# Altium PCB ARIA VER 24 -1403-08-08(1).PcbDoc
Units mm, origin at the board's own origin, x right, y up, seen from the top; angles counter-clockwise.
Board outline 174.25 x 98.25 mm, 2 copper layers (Top Layer, Bottom Layer), stack 2.06 mm thick; 9 components, 12 nets, 45 pads, 0 vias.
Unrouted connection lines stored in the file: 13.
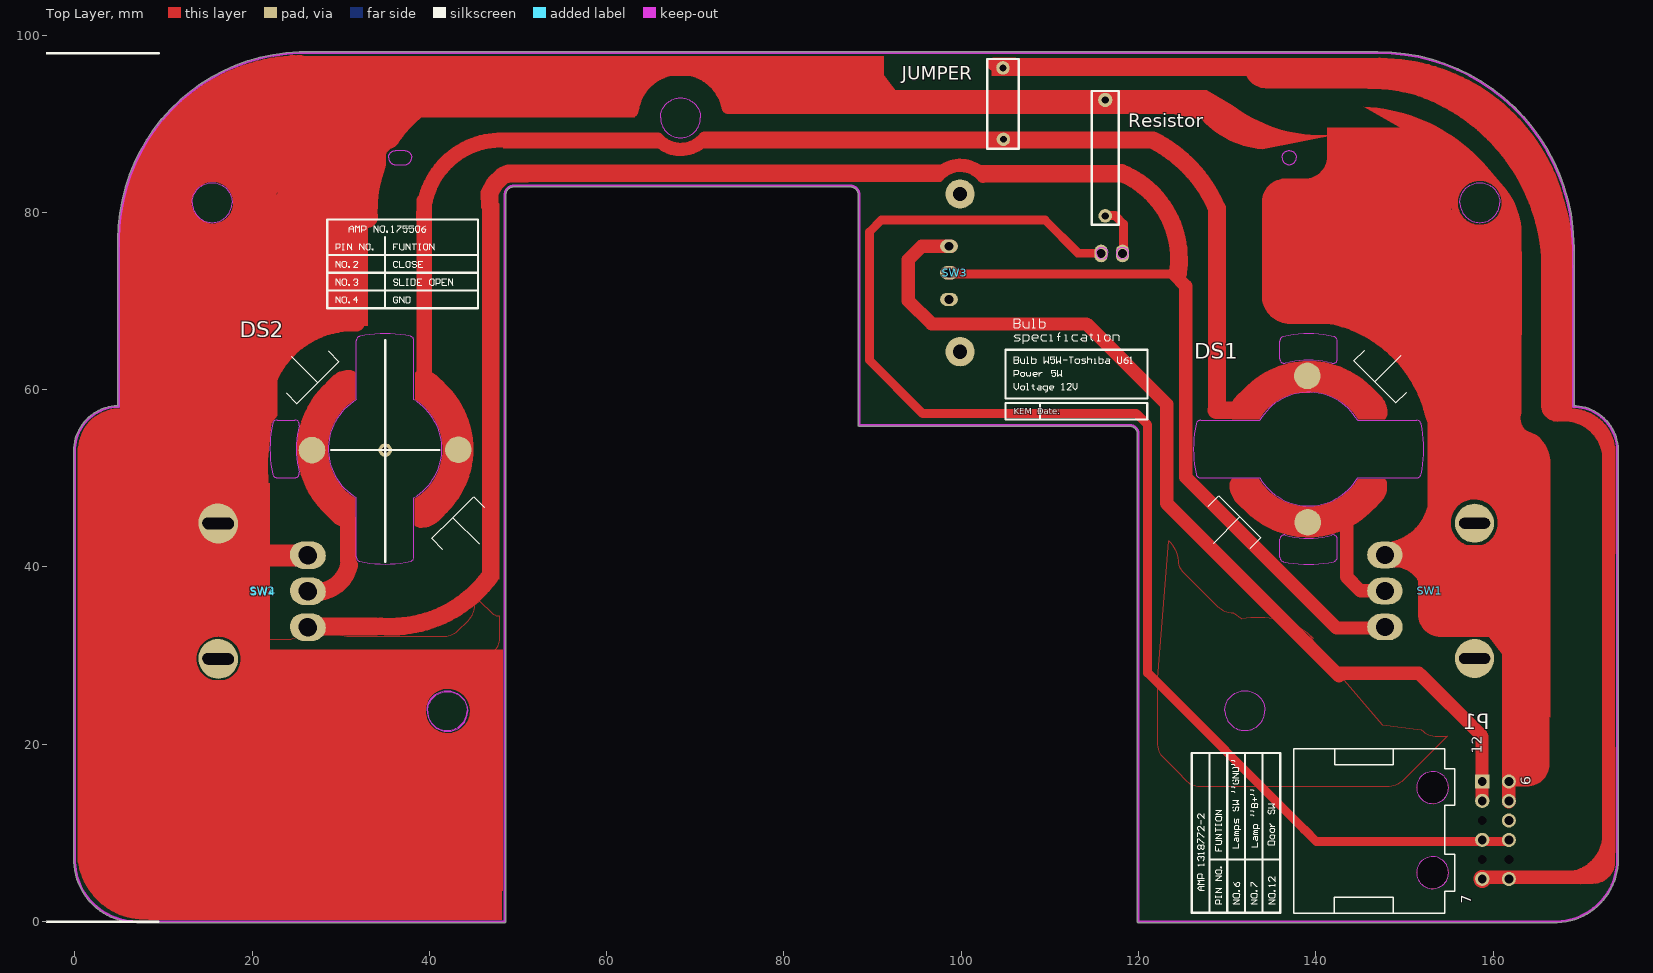
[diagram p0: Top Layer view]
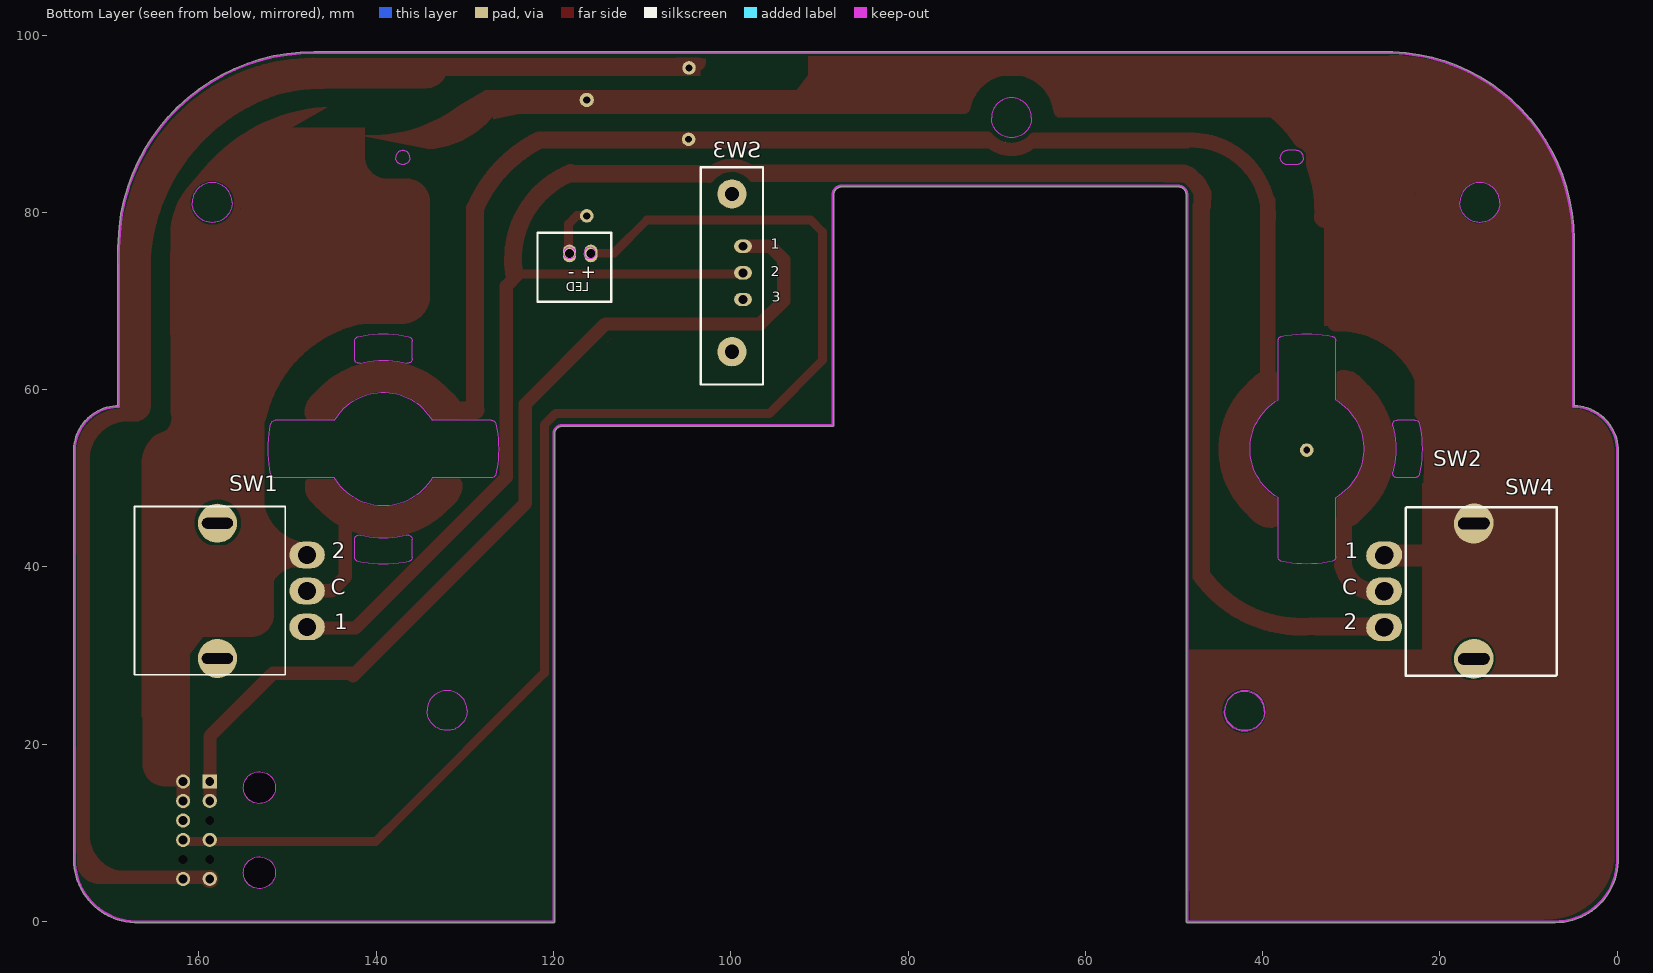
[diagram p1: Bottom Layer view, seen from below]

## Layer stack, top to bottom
Top Solder: solder mask 0.0102, Solder Resist, Dk 3.5
Top Layer: signal copper 0.16
Dielectric1: core 1.6, FR-4, Dk 4.8
Bottom Layer: signal copper 0.3
Bottom Solder: solder mask 0.0102, Solder Resist, Dk 3.5

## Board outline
655 vertices, not listed, extent -0.129,-0.129 174.126,98.126

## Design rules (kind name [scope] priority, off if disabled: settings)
AssemblyTestPointUsage [All] p1 off:
AssemblyTestpoint [All] p1 off: testpointundercomponent=TRUE minsize=1.016 maxsize=2.54 preferedsize=1.524 minholesize=0 maxholesize=1.016 preferedholesize=0.813 testpointgrid=0.025 usegrid=TRUE gridtolerance=0 allowsidetop=TRUE allowsidebottom=TRUE
Clearance Clearance_3 [All] p1: gap=0.254 ignorepadtopadclearanceinfootprint=FALSE except(0: Arc-Hole Track-Hole SMDPad-Hole THPad-Hole Via-Hole Fill-Hole Poly-Hole Region-Hole Text-Hole)
Clearance Clearance_2 [All] p2: gap=0.254 ignorepadtopadclearanceinfootprint=FALSE except(0: Arc-Hole Track-Hole SMDPad-Hole THPad-Hole Via-Hole Fill-Hole Poly-Hole Region-Hole Text-Hole)
Clearance Clearance_1 [All] p3: gap=0.254 ignorepadtopadclearanceinfootprint=FALSE except(0: Arc-Hole Track-Hole SMDPad-Hole THPad-Hole Via-Hole Fill-Hole Poly-Hole Region-Hole Text-Hole)
Clearance [All] p4: gap=0.01 ignorepadtopadclearanceinfootprint=FALSE except(0: Arc-Hole Track-Hole SMDPad-Hole THPad-Hole Via-Hole Fill-Hole Poly-Hole Region-Hole Text-Hole)
ComponentClearance [All] p1 off: gap=0 collisioncheckmode=3 verticalgap=0 showdistances=FALSE
DiffPairsRouting [All] p1 off: maxlimit=0.254 minlimit=0.254 mostfreqgap=0.254 toplayer_minwidth=0.381 toplayer_maxwidth=0.381 toplayer_prefwidth=0.381 bottomlayer_minwidth=0.381 bottomlayer_maxwidth=0.381 bottomlayer_prefwidth=0.381 maxuncoupledlength=12.7
FabricationTestPointUsage [All] p1 off: valid=0 allowmultiple=FALSE
FabricationTestpoint [All] p1 off: side=3 testpointundercomponent=TRUE minsize=1.016 maxsize=2.54 preferedsize=1.524 minholesize=0 maxholesize=1.016 preferedholesize=0.813 testpointgrid=0.025 allowsidetop=TRUE allowsidebottom=TRUE usegrid=TRUE gridtolerance=0
FanoutControl Fanout_BGA [IsBGA] p1 off: bgadir=Out bgaviamode=Centered fanoutstyle=Auto fanoutdirection=Alternating viagrid=0.025 // Fanout_BGA (Default Rule)
FanoutControl Fanout_LCC [IsLCC] p2 off: bgadir=Out bgaviamode=Centered fanoutstyle=Auto fanoutdirection=Alternating viagrid=0.025 // Fanout_LCC (Default Rule)
FanoutControl Fanout_SOIC [IsSOIC] p3 off: bgadir=Out bgaviamode=Centered fanoutstyle=Auto fanoutdirection=Alternating viagrid=0.025 // Fanout_SOIC (Default Rule)
FanoutControl Fanout_Small [(CompPinCount < 5)] p4 off: bgadir=Out bgaviamode=Centered fanoutstyle=Auto fanoutdirection=OutThenIn viagrid=0.025 // Fanout_Small (Default Rule)
FanoutControl Fanout_Default [All] p5 off: bgadir=Out bgaviamode=Centered fanoutstyle=Auto fanoutdirection=Alternating viagrid=0.025 // Fanout_Default (Default Rule)
Height [All] p1 off: minheight=0 maxheight=25.4 prefheight=12.7
HoleSize [All] p1 off: absolutevalues=TRUE maxlimit=2.54 minlimit=0.025 maxpercent=80.000 minpercent=20.000
HoleToHoleClearance [All] p1 off: gap=0 allowstackedmicrovias=FALSE
LayerPairs [All] p1 off: enforce=TRUE
MatchedLengths [All] p1: tolerance=0.5 checknetsindiffpair=TRUE checkdiffpairvsdiffpair=FALSE checkxsignals=FALSE checkothers=FALSE
MinimumSolderMaskSliver [All] p1 off: minsoldermaskwidth=0.254
NetAntennae [All] p1 off: netantennaetolerance=0
ParallelSegment [Not All] p1 off: limit=254 gap=0.1
PasteMaskExpansion [All] p1 off: expansion=0
PlaneClearance [All] p1 off: clearance=0.1
PlaneConnect [All] p1: planeconnectstyle=Direct reliefexpansion=0.508 reliefentries=4 reliefconductorwidth=0.254 reliefairgap=0.254
PolygonConnect [All] p1: connectstyle=Direct reliefconductorwidth=0 reliefentries=4 polygonreliefangle="90 Angle" airgapwidth=0
PolygonConnect PolygonConnect_2 [All vs IsNamedPolygon('NETDS1_2_L01_P016')] p2 off: connectstyle=Direct reliefconductorwidth=0.254 reliefentries=4 polygonreliefangle="90 Angle" airgapwidth=0.254
PolygonConnect PolygonConnect_3 [All] p3 off: connectstyle=Direct reliefconductorwidth=0.254 reliefentries=4 polygonreliefangle="90 Angle" airgapwidth=0.254
PolygonConnect PolygonConnect_1 [All vs IsNamedPolygon('NETDS1_2_L01_P002')] p4 off: connectstyle=Direct reliefconductorwidth=0.254 reliefentries=4 polygonreliefangle="90 Angle" airgapwidth=0.254
RoutingCorners [All] p1 off: cornerstyle=Round minsetback=2.54 maxsetback=2.54
RoutingLayers [All] p1 off: top layer_v5=TRUE bottom layer_v5=TRUE
RoutingPriority [All] p1 off: routingpriority=0
RoutingTopology [All] p1 off: topology=Shortest
RoutingVias [All] p1: holewidth=0.711 width=1.27 viastyle="Through Hole" minholewidth=0.5 minwidth=0.5 maxholewidth=5 maxwidth=10
ShortCircuit [All] p1 off: allowed=TRUE
SilkToBoardRegionClearance [All] p1 off:
SilkToSilkClearance [All] p1 off: silktosilkclearance=0.254
SilkToSolderMaskClearance SilkscreenOverComponentPads [IsPad] p1 off: minsilkscreentomaskgap=0.254 clearancetoexposedcopper=TRUE
SolderMaskExpansion [All] p1 off: expansion=0.102 istentingtop=FALSE
UnRoutedNet [All] p1 off:
Width [All] p1: maxlimit=10 minlimit=0.1 preferedwidth=1
1 further rules are at their usual default settings.

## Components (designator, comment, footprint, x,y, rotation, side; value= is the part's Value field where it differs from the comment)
DS1 "LAMP 1" "LAMP 1"#1 139.067,53.289 r0 top
DS2 "LAMP 1" "LAMP 1"#2 35.013,53.199 r90 top locked
JUMPER "Comment" PCBComponent_1#1 106.487,82.703 r0 top
P1 "CON 31" "CON 63" 158.773,15.805 r90 top locked
Resistor "Comment" PCBComponent_1#2 116.244,85.826 r0 top
SW1 "SW-SPDT" "SWITCH 6"#1 147.801,33.228 r90 top locked
SW2 "SW-SPDT" "SWITCH 6"#2 26.253,41.377 r270 top locked
SW3 "KEY 1" "SWITCH 7" 98.62,76.177 r270 top locked
SW4 "SW-SPDT" "SWITCH 6"#2 26.313,41.27 r270 top locked (schematic designator SW2)

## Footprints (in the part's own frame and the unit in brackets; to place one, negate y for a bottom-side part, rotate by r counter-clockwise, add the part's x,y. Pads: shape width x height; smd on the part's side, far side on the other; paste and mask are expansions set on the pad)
"CON 63" [mm]
  rect 1.6x1.6 hole 1: 1(0,0)
  round 1.6 hole 1: 2(-0.005,-3.002) 3(-2.2,0) 4(-2.205,-3.002) 6(-4.405,-3.002) 7(-6.599,0) 8(-6.604,-3.002) 11(-10.998,0) 12(-11.003,-3.002)
  round 0 hole 1: 5(-4.399,0) 9(-8.798,0) 10(-8.804,-3.002)
  round 3.6 hole 3.6: ""(-10.299,5.598) ""(-0.699,5.598)
  Keep-Out Layer circle w0.1: c-10.299,5.598 r1.8
  Keep-Out Layer circle w0.1: c-0.699,5.598 r1.8
  silkscreen extent -14.88,3.09 3.68,21.24
"LAMP 1"#1 [mm]
  round 3 smd: 1(-0.018,8.258) 2(0.018,-8.258)
  Top Layer region: -4.422,5.185 -4.44,5.094 -4.492,5.017 -4.492,5.017 -5.093,4.415 -5.093,3.955 -5.089,3.938 -5.079,3.923 -5.079,3.923 -5.464,3.363 -8.484,3.367 -8.673,3.649 -8.739,3.982 -8.739,3.982 -8.739,4.197 -8.546,5.169 -7.995,5.993 -7.995,5.993 -7.336,6.653
  Top Layer region: 4.669,5.171 4.687,5.08 4.738,5.003 4.738,5.003 5.34,4.402 5.34,3.942 5.336,3.924 5.326,3.909 5.326,3.909 5.711,3.349 8.731,3.353 8.92,3.635 8.986,3.968 8.986,3.968 8.986,4.183 8.793,5.155 8.242,5.979 8.242,5.979 7.582,6.639
  Top Layer region: 4.645,-5.193 4.663,-5.102 4.714,-5.025 4.714,-5.025 5.316,-4.423 5.316,-3.963 5.312,-3.946 5.302,-3.931 5.302,-3.931 5.687,-3.371 8.707,-3.375 8.896,-3.657 8.962,-3.99 8.962,-3.99 8.962,-4.205 8.768,-5.177 8.218,-6.001 8.218,-6.001 7.558,-6.66
  Top Layer region: -4.446,-5.179 -4.464,-5.088 -4.516,-5.011 -4.516,-5.011 -5.117,-4.41 -5.117,-3.95 -5.114,-3.932 -5.104,-3.917 -5.104,-3.917 -5.488,-3.357 -8.509,-3.361 -8.697,-3.643 -8.763,-3.976 -8.763,-3.976 -8.763,-4.191 -8.57,-5.163 -8.019,-5.987 -8.019,-5.987 -7.36,-6.647
  Top Layer lines w3.5: -6.373,-5.115 ccw(c0.097,0.101) 6.47,-5.232 ; -6.247,5.224 cw(c0.126,-0.109) -1.236,8.089 cw(c0.126,-0.109) 6.595,5.107
  Keep-Out Layer lines w0.1: -2.496,9.703 cw(c0.124,0.001) 2.744,9.703 ; -2.496,9.703 cw(c-2.626,10.186) -3.126,10.186 -3.126,12.194 cw(c-2.626,12.194) -2.736,12.682 cw(c0.124,0.001) 2.984,12.682 cw(c2.874,12.194) 3.374,12.194 3.374,10.186 cw(c2.874,10.186) 2.744,9.703 ; -12.557,-2.859 ccw(c-12.07,-2.749) -12.07,-3.249 -5.389,-3.249 ccw(c0.124,0.001) 5.638,-3.249 12.318,-3.249 ccw(c12.318,-2.749) 12.806,-2.859 ccw(c0.124,0.001) 12.806,2.861 ccw(c12.318,2.751) 12.318,3.251 5.638,3.251 ccw(c0.124,0.001) -5.389,3.251 -12.07,3.251 ccw(c-12.07,2.751) -12.557,2.861 ccw(c0.124,0.001) -12.557,-2.859 ; -3.126,-12.193 ccw(c-2.626,-12.193) -2.736,-12.681 ccw(c0.124,0.001) 2.984,-12.681 ccw(c2.874,-12.193) 3.374,-12.193 3.374,-10.185 ccw(c2.874,-10.185) 2.744,-9.702 cw(c0.124,0.001) -2.496,-9.702 ccw(c-2.626,-10.185) -3.126,-10.185 -3.126,-12.193
  silkscreen extent -11.19,-11.19 11.17,11.17
"LAMP 1"#2 [mm]
  round 3 smd: 1(-0.018,8.258) 2(0.018,-8.258)
  Top Layer region: -4.446,-5.179 -4.464,-5.088 -4.516,-5.011 -4.516,-5.011 -5.117,-4.41 -5.117,-3.95 -5.114,-3.932 -5.104,-3.917 -5.104,-3.917 -5.488,-3.357 -8.509,-3.361 -8.697,-3.643 -8.763,-3.976 -8.763,-3.976 -8.763,-4.191 -8.57,-5.163 -8.019,-5.987 -8.019,-5.987 -7.36,-6.647
  Top Layer region: 4.645,-5.193 4.663,-5.102 4.714,-5.025 4.714,-5.025 5.316,-4.423 5.316,-3.963 5.312,-3.946 5.302,-3.931 5.302,-3.931 5.687,-3.371 8.707,-3.375 8.896,-3.657 8.962,-3.99 8.962,-3.99 8.962,-4.205 8.768,-5.177 8.218,-6.001 8.218,-6.001 7.558,-6.66
  Top Layer region: 4.669,5.171 4.687,5.08 4.738,5.003 4.738,5.003 5.34,4.402 5.34,3.942 5.336,3.924 5.326,3.909 5.326,3.909 5.711,3.349 8.731,3.353 8.92,3.635 8.986,3.968 8.986,3.968 8.986,4.183 8.793,5.155 8.242,5.979 8.242,5.979 7.582,6.639
  Top Layer region: -4.422,5.185 -4.44,5.094 -4.492,5.017 -4.492,5.017 -5.093,4.415 -5.093,3.955 -5.089,3.938 -5.079,3.923 -5.079,3.923 -5.464,3.363 -8.484,3.367 -8.673,3.649 -8.739,3.982 -8.739,3.982 -8.739,4.197 -8.546,5.169 -7.995,5.993 -7.995,5.993 -7.336,6.653
  Top Layer lines w3.5: -6.247,5.224 cw(c0.126,-0.109) 6.595,5.107 ; -6.373,-5.115 ccw(c0.097,0.101) 6.47,-5.232
  Keep-Out Layer lines w0.1: -2.736,12.682 cw(c0.124,0.001) 2.984,12.682 cw(c2.874,12.194) 3.374,12.194 3.374,10.186 cw(c2.874,10.186) 2.744,9.703 ccw(c0.124,0.001) -2.496,9.703 cw(c-2.626,10.186) -3.126,10.186 -3.126,12.194 cw(c-2.626,12.194) -2.736,12.682 ; -12.07,3.251 ccw(c-12.07,2.751) -12.557,2.861 ccw(c0.124,0.001) -12.557,-2.859 ccw(c-12.07,-2.749) -12.07,-3.249 -5.389,-3.249 ccw(c0.124,0.001) 5.638,-3.249 12.318,-3.249 ccw(c12.318,-2.749) 12.806,-2.859 ccw(c0.124,0.001) 12.806,2.861 ccw(c12.318,2.751) 12.318,3.251 5.638,3.251 ccw(c0.124,0.001) -5.389,3.251 -12.07,3.251
  silkscreen extent -11.19,-11.19 11.17,11.17
PCBComponent_1#1 [mil]
  round 60 hole 30: 4(-70,535) 5(-68.1,217.94)
  silkscreen extent -140,176 0,575
PCBComponent_1#2 [mil]
  round 62.99 hole 31.5: 6(0,270)
  round 60 hole 31.5: 7(0,-245)
  silkscreen extent -60,-285 60,310
"SWITCH 6"#1 [mm]
  oval 3x4 hole 2: 1(0,0) 2(4.058,0.002) 3(8.12,0.003)
  round 4.4 hole 3.5 slot 1.2 at 0 deg: ""(-3.55,-10.108) ""(11.7,-10.109)
"SWITCH 6"#2 [mm]
  oval 3x4 hole 2: 1(0,0) 2(4.058,0.002) 3(8.12,0.003)
  round 4.4 hole 3.5 slot 1.2 at 0 deg: ""(-3.58,-10.108) ""(11.699,-10.109)
"SWITCH 7" [mm]
  oval 1.5x2 hole 1: 1(0,0) 2(3,0.002) 3(6,0.002)
  round 3.3 hole 1.6: ""(-5.9,1.252) ""(11.9,1.252)

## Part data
SW1 SW2 SW4: "SPDT Subminiature Toggle Switch, Right Angle Mounting, Vertical Actuation"

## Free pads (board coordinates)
  round 1.524 hole 0.762: 0(35.021,53.183)
  oval 1.5x2 hole 1: 1(115.772,75.367) 2(118.191,75.367)

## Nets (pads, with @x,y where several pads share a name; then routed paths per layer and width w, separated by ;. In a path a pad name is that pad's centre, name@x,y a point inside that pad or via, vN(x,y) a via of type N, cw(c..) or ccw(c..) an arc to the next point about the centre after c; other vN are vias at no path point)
BAT_12V: DS1.1 DS2.2 JUMPER.5 P1.11 | length 143.9
  Top Layer w0.5: 168.17,5.393 ccw(c168.112,9.864) 172.542,10.468
  Top Layer w0.7: 167.985,56.769 cw(c167.985,52.064) 172.67,51.636
  Top Layer w0.85: 168.312,57.362 cw(c168.312,52.657) 172.998,52.228
  Top Layer w1.5: 65.756,88.253 ccw(c68.354,90.598) 71.076,88.397 ; P1.11@158.665,4.981 169.943,4.981
  Top Layer w1.7: 39.327,79.312 cw(c48.082,79.406) 48.317,88.158 ; 39.42,60.916 39.42,81.315
  Top Layer w2: 121.64,88.124 cw(c114.695,74.419) 128.741,80.646 ; 128.808,57.665 131.254,57.665 ; 128.843,57.891 128.843,80.462
  Top Layer w3.5: 146.13,95.672 cw(c146.093,74.442) 167.324,74.405
DOOR: P1.1 P1.3 SW3.1 | length 108.6
  Top Layer w1.5: SW3.1@98.819,76.181 95.549,76.181 94.028,74.66 94.028,70.037 96.655,67.411 114.127,67.411 123.18,58.358 123.18,47.157 142.614,27.723 ; 142.625,28 151.625,28 ; 151.75,27.875 158.75,20.875 P1.1@158.75,15.875 ; P1.3@158.75,13.75 P1.1@158.75,15.75
GND: P1.2 P1.4 Resistor.6 SW1.3 SW4.1 | length 185.9
  Top Layer w0.254: SW1.3@148.11,40.022 cw(c148.819,36.838) 151.715,38.338 ; 163.055,57.367 ccw(c165.103,56.819) 164.811,54.719
  Top Layer w0.75: 161.325,81.072 ccw(c158.484,81.072) 161.325,81.072
  Top Layer w1.5: 62.862,91.454 cw(c68.318,90.755) 73.712,91.83 ; SW1.3@147.628,41.986 ccw(c147.349,48.131) 153.5,48.131 ; 161.273,44.974 cw(c157.877,44.974) 161.273,44.993 ; P1.4@161.75,13.5 P1.2@161.75,15.875 ; P1.2 161.775,30.935
  Top Layer w2: 139.866,68.662 cw(c138.721,53.694) 153.293,57.298 cw(c138.721,53.694) 153.316,57.206 156.394,48.526
  Top Layer w2.5: 22.065,41.27 SW4.1 ; 32.943,79.465 cw(c47.643,80.269) 33.873,85.478 ; 35.411,88.461 cw(c47.643,80.269) 48.239,94.979
  Top Layer w3: 6.505,76.542 cw(c25.777,76.983) 25.336,96.256 ; 6.585,57.1 ccw(c15.499,59.978) 14.885,50.631
  Bottom Layer w0.254: SW1.3 147.829,40.269 ccw(c148.082,40.276) 147.829,40.266 147.833,40.167 147.903,40.097 147.977,40.022 148.082,40.022 SW1.3@148.11,40.022
LED+: P1.7 P1.8 pad.1 | length 151
  Top Layer w1: 113.16,75.419 109.445,79.135 90.996,79.135 89.649,77.787 89.649,63.311 95.661,57.298 119.706,57.298 ; 119.78,57.268 121.022,56.026 121.022,28.039 138.667,10.394 ; 138.699,10.394 140.08,9.013 P1.8@161.832,9.013
NetDS1_1:  | length 76.1
  Top Layer w0.254: 77.744,95.935 77.765,95.931
  Top Layer w0.8: 44.962,23.94 ccw(c42.083,23.748) 44.968,23.746
  Top Layer w2: 21.026,57.864 cw(c31.442,57.146) 31.742,67.583 ; 26.79,75.867 cw(c43.665,74.286) 34.331,88.434 ; 19.693,29.642 ccw(c16.207,29.642) 19.693,29.642
  Top Layer w2.5: 33.873,85.478 33.845,85.506 33.845,86.849 33.89,86.894 33.893,86.949 33.937,86.992 33.944,87.048 33.982,87.085 33.982,87.13 34.014,87.175 34.014,87.236 34.05,87.279 34.05,87.341 34.089,87.381 34.089,87.397 34.999,88.307 35.046,88.307 35.088,88.345 35.149,88.345 35.193,88.379 35.253,88.379 35.28,88.406 35.297,88.409 35.3,88.41 35.306,88.41 35.335,88.415 35.378,88.458 35.411,88.461
  Top Layer w3.5: 137.831,61.378 139.12,61.378
NetDS1_2: SW1.2 | length 12.7
  Top Layer w1.5: 143.495,45.886 143.495,38.865 145.034,37.325 147.76,37.325 SW1.2
  Top Layer w2: 145.537,48.057 146.225,47.855 146.229,47.854
NetDS2_2: SW4.2 | length 6.5
  Top Layer w2: SW4.2@25.855,37.413 ccw(c27.194,40.993) 30.928,40.175
NetP1_1: 
NetP1_2: 
NetSW1_3: SW4.3 SW4.@16.204,29.572 | length 2.2
  Top Layer w2: 48.783,84.335 48.878,84.365 48.927,84.379 50.928,84.382
NewNet: 
PUSH_B: SW1.1 SW2.3 SW3.2 | length 127
  Top Layer w1: SW3.2@98.431,73.055 122.226,73.055 ; 121.269,73.055 123.887,73.055
  Top Layer w1.5: 97.403,84.158 cw(c99.9,82) 102.458,84.085 ; 123.958,73.058 125.328,71.688 125.328,50.111 142.339,33.101 SW1.1@148.565,33.101
  Top Layer w2: SW2.3@25.536,33.29 33.899,33.29 ; 34.499,33.301 ccw(c35.601,47.216) 46.867,38.976 ; 46.849,80.731 cw(c56.051,81.916) 46.776,82.145 47.398,83.265 48.207,84.074 48.272,84.123 48.783,84.335 ; 118.079,84.441 cw(c114.044,74.72) 124.446,73.12
pads on no net: DS1.2 DS2.1 JUMPER.4 P1. P1.5 P1.6 P1.9 P1.10 P1.12 Resistor.7 SW1. SW2. SW2.1 SW2.2 SW3. SW3.3 SW4.@16.205,44.851
copper on no net: | length 206.1
  Top Layer w0.254: 119.719,57.268 119.78,57.268
  Top Layer w0.7: 103.285,97.037 147.278,97.037 ; 144.619,94.645 cw(c144.583,73.414) 165.813,73.378 ; 147.193,97.094 cw(c147.156,75.864) 168.387,75.827 ; 168.551,57.722 168.551,76.236 ; 168.779,57.513 cw(c168.779,52.808) 173.465,52.379 ; 173.393,19.608 173.465,19.536 173.465,8.503 ; 173.393,41.532 173.465,41.603 173.465,52.637
  Top Layer w0.899: 18.316,81.078 ccw(c15.518,81.078) 18.316,81.078
  Top Layer w1: 116.287,79.632 117.351,79.632 118.296,78.688 118.296,75.401
  Top Layer w1.5: 98.622,73.176 98.872,73.176
  Top Layer w2: 1.387,53.424 cw(c5.033,53.22) 5.237,56.865 ; 7.134,46.395 cw(c13.519,43.667) 12.544,50.541 ; 158.773,4.807 158.779,4.802
  Top Layer w2.1: 1.372,6.977 ccw(c7.909,7.843) 8.774,1.306

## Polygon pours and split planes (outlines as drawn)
no net on Top Layer "Top Layer-No Net 1" (solid, remove dead copper, shelved, pour order 25): 123.424,42.969 cw(c120.859,40.404) 124.486,40.404 ccw(c126.036,40.645) 124.929,39.534 128.894,35.569 ccw(c130.69,37.365) 130.69,34.825 131.622,34.174 cw(c133.425,24.405) 139.059,32.587 139.718,31.927 cw(c142.481,38.038) 139.356,32.104 140.091,31.1 ccw(c144.972,32.438) 142.466,28.041 147.517,22.213 151.912,21.629 ccw(c153.708,23.425) 153.708,20.885 154.801,20.885 149.855,15.94 cw(c148.06,17.736) 148.059,15.196 126.924,15.196 cw(c126.924,17.203) 125.505,15.784 124.342,16.947 122.898,18.391 cw(c124.694,20.187) 122.154,20.187 122.154,27.449
NetSW1_3 on Top Layer "Top Layer-No Net" (solid, remove dead copper, shelved, pour order 0): 16.395,33.077 3.958,33.077 ccw(c3.958,30.537) 1.418,30.537 1.418,24.413 1.418,7.206 ccw(c3.958,7.206) 2.162,5.41 3.609,3.963 5.238,2.334 ccw(c7.035,4.13) 7.035,1.59 19.996,1.59 44.462,1.59 ccw(c44.462,4.13) 47.002,4.13 47.002,9.095 47.002,29.701 cw(c48.299,29.701) 47.382,30.619 ccw(c46.06,31.941) 47.93,31.941 47.93,34.407 cw(c47.93,35.509) 47.15,34.73 45.702,36.123 45.054,35.688 cw(c42.514,35.688) 44.31,33.892 43.137,32.718 cw(c41.704,34.151) 41.704,32.125 36.427,32.125 30.906,32.125 cw(c30.906,34.665) 29.11,32.869 27.572,34.407 25.668,32.504 cw(c23.872,34.3) 23.872,31.76 20.816,31.76

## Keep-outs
Keep-Out Layer:
  lines w0.1: 88.499,55.998 118.999,55.998 ; 115.241,75.468 115.239,75.412 115.241,75.356 115.247,75.3 ; 115.244,75.495 115.254,75.55 115.267,75.605 115.284,75.658 ; 115.246,75.3 115.26,75.245 115.277,75.192 115.298,75.141 ; 115.291,75.676 115.316,75.727 115.343,75.775 115.375,75.821 ; 115.303,75.127 115.327,75.077 115.355,75.029 115.386,74.982 ; 115.399,74.969 115.436,74.927 ; 115.399,75.847 115.439,75.886 115.482,75.922 115.527,75.954 115.574,75.984 ; 115.456,74.901 115.499,74.865 115.544,74.833 ; 115.556,75.969 115.605,75.996 115.656,76.018 115.709,76.037 ; 115.556,74.824 115.607,74.801 115.66,74.782 115.713,74.767 ; 115.702,74.767 115.757,74.755 115.812,74.747 115.868,74.743 115.924,74.743 115.979,74.747 116.035,74.755 116.089,74.767 ; 115.719,76.039 115.774,76.047 115.83,76.051 115.886,76.051 115.942,76.047 ; 115.911,76.045 115.967,76.037 116.021,76.026 ; 116.023,76.032 116.077,76.016 116.129,75.997 116.18,75.975 ; 116.085,74.761 116.136,74.783 116.185,74.81 116.233,74.839 ; 116.193,75.967 116.267,75.927 116.335,75.878 ; 116.237,74.844 116.282,74.877 116.324,74.913 116.365,74.951 116.402,74.993 ; 116.323,75.879 116.366,75.843 116.406,75.804 ; 116.388,75.82 116.434,75.769 116.482,75.697 ; 116.409,75.001 116.44,75.047 116.468,75.095 116.492,75.145 116.513,75.197 116.53,75.25 ; 116.486,75.676 116.51,75.626 ; 116.521,75.581 116.546,75.531 ; 116.536,75.278 116.546,75.333 116.552,75.389 ; 116.55,75.479 116.552,75.423 ; 117.539,75.448 117.545,75.504 117.554,75.559 117.568,75.613 ; 117.54,75.438 117.538,75.382 117.54,75.326 117.546,75.271 117.556,75.216 117.569,75.162 ; 117.564,75.178 117.585,75.126 117.609,75.076 117.637,75.027 ; 117.566,75.615 117.591,75.666 ; 117.583,75.661 117.611,75.709 117.642,75.755 117.676,75.799 117.714,75.841 ; 117.653,75.013 117.687,74.969 117.724,74.928 ; 117.681,75.817 117.721,75.856 117.764,75.892 ; 117.695,74.964 117.738,74.928 117.783,74.895 117.831,74.866 117.88,74.84 ; 117.776,75.905 117.821,75.938 117.868,75.968 117.918,75.994 117.969,76.017 ; 117.882,74.84 117.933,74.817 117.986,74.798 118.039,74.782 118.094,74.771 118.149,74.763 ; 117.953,76.016 118.007,76.032 118.061,76.043 118.117,76.051 118.172,76.055 118.228,76.055 118.284,76.051 118.339,76.043 118.394,76.032 ; 118.094,74.767 118.15,74.763 118.206,74.763 118.262,74.767 118.317,74.775 118.372,74.786 118.425,74.802 ; 118.207,401 118.346,400.926 ; 118.372,76.043 118.424,76.023 118.475,76.001 118.524,75.975 118.572,75.945 ; 118.421,74.798 118.474,74.817 118.525,74.84 118.574,74.866 118.621,74.895 118.666,74.928 ; 118.577,75.942 118.62,75.906 118.66,75.867 118.697,75.826 118.732,75.782 118.763,75.735 ; 118.679,74.937 118.714,74.981 118.745,75.027 118.773,75.076 118.797,75.126 118.818,75.178 118.836,75.231 ; 118.782,75.709 118.806,75.659 118.827,75.607 118.844,75.554 118.858,75.5 118.868,75.445 ; 118.83,75.184 118.843,75.238 118.853,75.293 118.859,75.349 118.861,75.405 118.859,75.461 118.853,75.516 ; 13.249,81.098 13.254,81.255 13.271,81.412 13.298,81.566 13.336,81.719 13.384,81.868 13.443,82.014 13.512,82.155 13.591,82.291 13.678,82.421 13.775,82.545 13.88,82.661 13.993,82.77 14.114,82.871 14.241,82.964 14.374,83.047 14.512,83.121 14.656,83.185 14.803,83.238 14.954,83.282 15.108,83.314 15.264,83.336 15.42,83.347 15.577,83.347 15.734,83.336 15.889,83.314 16.043,83.282 16.194,83.238 16.342,83.185 16.485,83.121 16.624,83.047 16.757,82.964 16.884,82.871 17.004,82.77 17.117,82.661 17.222,82.545 17.319,82.421 17.407,82.291 17.485,82.155 17.554,82.014 17.613,81.868 17.662,81.719 17.7,81.566 17.727,81.412 17.743,81.255 17.749,81.098 17.743,80.941 17.727,80.785 17.7,80.631 17.662,80.478 17.613,80.329 17.554,80.183 17.485,80.042 17.407,79.906 17.319,79.776 17.222,79.652 17.117,79.535 17.004,79.426 16.884,79.325 16.757,79.233 16.624,79.15 16.485,79.076 16.342,79.012 16.194,78.958 16.043,78.915 15.889,78.883 15.734,78.861 15.577,78.85 15.42,78.85 15.264,78.861 15.108,78.883 14.954,78.915 14.803,78.958 14.656,79.012 14.512,79.076 14.374,79.15 14.241,79.233 14.114,79.325 13.993,79.426 13.88,79.535 13.775,79.652 13.678,79.776 13.591,79.906 13.512,80.042 13.443,80.183 13.384,80.329 13.336,80.478 13.298,80.631 13.271,80.785 13.254,80.941 13.249,81.098 ; 35.399,86.15 35.403,86.094 35.411,86.039 35.423,85.984 35.438,85.93 35.457,85.878 35.48,85.827 35.506,85.778 35.536,85.73 35.568,85.685 35.604,85.642 35.643,85.602 35.685,85.565 35.729,85.53 35.775,85.499 35.823,85.471 35.873,85.447 35.925,85.426 35.978,85.409 36.032,85.395 36.087,85.385 36.143,85.38 36.199,85.378 37.199,85.378 37.255,85.38 37.31,85.385 37.365,85.395 37.419,85.409 37.472,85.426 37.524,85.447 37.574,85.471 37.623,85.499 37.669,85.53 37.713,85.565 37.754,85.602 37.793,85.642 37.829,85.685 37.862,85.73 37.892,85.778 37.918,85.827 37.941,85.878 37.96,85.93 37.975,85.984 37.987,86.039 37.994,86.094 37.998,86.15 37.998,86.206 37.994,86.261 37.987,86.317 37.975,86.371 37.96,86.425 37.941,86.477 37.918,86.528 37.892,86.578 37.862,86.625 37.829,86.67 37.793,86.713 37.754,86.753 37.713,86.791 37.669,86.825 37.623,86.856 37.574,86.884 37.524,86.909 37.472,86.929 37.419,86.947 37.365,86.96 37.31,86.97 37.255,86.976 37.199,86.978 36.199,86.978 36.143,86.976 36.087,86.97 36.032,86.96 35.978,86.947 35.925,86.929 35.873,86.909 35.823,86.884 35.775,86.856 35.729,86.825 35.685,86.791 35.643,86.753 35.604,86.713 35.568,86.67 35.536,86.625 35.506,86.578 35.48,86.528 35.457,86.477 35.438,86.425 35.423,86.371 35.411,86.317 35.403,86.261 35.399,86.206 35.399,86.15 ; 39.749,23.798 39.754,23.955 39.771,24.112 39.798,24.266 39.836,24.419 39.884,24.568 39.943,24.714 40.012,24.855 40.091,24.991 40.178,25.121 40.275,25.245 40.38,25.361 40.493,25.47 40.614,25.571 40.741,25.664 40.874,25.747 41.012,25.821 41.156,25.885 41.303,25.938 41.454,25.982 41.608,26.014 41.764,26.036 41.92,26.047 42.077,26.047 42.234,26.036 42.389,26.014 42.543,25.982 42.694,25.938 42.842,25.885 42.985,25.821 43.124,25.747 43.257,25.664 43.384,25.571 43.504,25.47 43.617,25.361 43.722,25.245 43.819,25.121 43.907,24.991 43.985,24.855 44.054,24.714 44.113,24.568 44.162,24.419 44.2,24.266 44.227,24.112 44.243,23.955 44.249,23.798 44.243,23.641 44.227,23.485 44.2,23.331 44.162,23.178 44.113,23.029 44.054,22.883 43.985,22.742 43.907,22.606 43.819,22.476 43.722,22.352 43.617,22.235 43.504,22.126 43.384,22.025 43.257,21.933 43.124,21.85 42.985,21.776 42.842,21.712 42.694,21.658 42.543,21.615 42.389,21.583 42.234,21.561 42.077,21.55 41.92,21.55 41.764,21.561 41.608,21.583 41.454,21.615 41.303,21.658 41.156,21.712 41.012,21.776 40.874,21.85 40.741,21.933 40.614,22.025 40.493,22.126 40.38,22.235 40.275,22.352 40.178,22.476 40.091,22.606 40.012,22.742 39.943,22.883 39.884,23.029 39.836,23.178 39.798,23.331 39.771,23.485 39.754,23.641 39.749,23.798 ; 39.809,23.692 39.814,23.535 39.831,23.379 39.858,23.224 39.896,23.072 39.944,22.923 40.003,22.777 40.072,22.636 40.151,22.5 40.238,22.37 40.335,22.246 40.44,22.129 40.553,22.02 40.673,21.919 40.8,21.827 40.934,21.744 41.072,21.67 41.216,21.606 41.363,21.552 41.514,21.509 41.668,21.476 41.823,21.454 41.98,21.443 42.137,21.443 42.294,21.454 42.449,21.476 42.603,21.509 42.754,21.552 42.902,21.606 43.045,21.67 43.184,21.744 43.317,21.827 43.444,21.919 43.564,22.02 43.677,22.129 43.782,22.246 43.879,22.37 43.967,22.5 44.045,22.636 44.114,22.777 44.173,22.923 44.222,23.072 44.259,23.224 44.287,23.379 44.303,23.535 44.309,23.692 44.303,23.849 44.287,24.005 44.259,24.16 44.222,24.312 44.173,24.462 44.114,24.607 44.045,24.748 43.967,24.884 43.879,25.015 43.782,25.138 43.677,25.255 43.564,25.364 43.444,25.465 43.317,25.557 43.184,25.641 43.045,25.714 42.902,25.778 42.754,25.832 42.603,25.875 42.449,25.908 42.294,25.93 42.137,25.941 41.98,25.941 41.823,25.93 41.668,25.908 41.514,25.875 41.363,25.832 41.216,25.778 41.072,25.714 40.934,25.641 40.8,25.557 40.673,25.465 40.553,25.364 40.44,25.255 40.335,25.138 40.238,25.015 40.151,24.884 40.072,24.748 40.003,24.607 39.944,24.462 39.896,24.312 39.858,24.16 39.831,24.005 39.814,23.849 39.809,23.692 ; 66.079,90.665 66.084,90.508 66.101,90.351 66.128,90.197 66.166,90.044 66.215,89.895 66.273,89.749 66.342,89.608 66.421,89.472 66.509,89.342 66.605,89.218 66.71,89.102 66.823,88.992 66.944,88.892 67.071,88.799 67.204,88.716 67.342,88.642 67.486,88.578 67.634,88.525 67.784,88.481 67.938,88.449 68.094,88.427 68.25,88.416 68.407,88.416 68.564,88.427 68.72,88.449 68.873,88.481 69.024,88.525 69.172,88.578 69.315,88.642 69.454,88.716 69.587,88.799 69.714,88.892 69.834,88.992 69.947,89.102 70.052,89.218 70.149,89.342 70.237,89.472 70.315,89.608 70.384,89.749 70.443,89.895 70.492,90.044 70.53,90.197 70.557,90.351 70.573,90.508 70.579,90.665 70.573,90.821 70.557,90.978 70.53,91.132 70.492,91.285 70.443,91.434 70.384,91.58 70.315,91.721 70.237,91.857 70.149,91.987 70.052,92.111 69.947,92.228 69.834,92.337 69.714,92.438 69.587,92.53 69.454,92.613 69.315,92.687 69.172,92.751 69.024,92.804 68.873,92.848 68.72,92.88 68.564,92.902 68.407,92.913 68.25,92.913 68.094,92.902 67.938,92.88 67.784,92.848 67.634,92.804 67.486,92.751 67.342,92.687 67.204,92.613 67.071,92.53 66.944,92.438 66.823,92.337 66.71,92.228 66.605,92.111 66.509,91.987 66.421,91.857 66.342,91.721 66.273,91.58 66.215,91.434 66.166,91.285 66.128,91.132 66.101,90.978 66.084,90.821 66.079,90.665 ; 129.749,23.798 129.754,23.955 129.771,24.112 129.798,24.266 129.836,24.419 129.884,24.568 129.943,24.714 130.012,24.855 130.091,24.991 130.178,25.121 130.275,25.245 130.38,25.361 130.493,25.47 130.614,25.571 130.741,25.664 130.874,25.747 131.012,25.821 131.156,25.885 131.303,25.938 131.454,25.982 131.608,26.014 131.764,26.036 131.92,26.047 132.077,26.047 132.234,26.036 132.389,26.014 132.543,25.982 132.694,25.938 132.842,25.885 132.985,25.821 133.124,25.747 133.257,25.664 133.384,25.571 133.504,25.47 133.617,25.361 133.722,25.245 133.819,25.121 133.907,24.991 133.985,24.855 134.054,24.714 134.113,24.568 134.162,24.419 134.2,24.266 134.227,24.112 134.243,23.955 134.249,23.798 134.243,23.641 134.227,23.485 134.2,23.331 134.162,23.178 134.113,23.029 134.054,22.883 133.985,22.742 133.907,22.606 133.819,22.476 133.722,22.352 133.617,22.235 133.504,22.126 133.384,22.025 133.257,21.933 133.124,21.85 132.985,21.776 132.842,21.712 132.694,21.658 132.543,21.615 132.389,21.583 132.234,21.561 132.077,21.55 131.92,21.55 131.764,21.561 131.608,21.583 131.454,21.615 131.303,21.658 131.156,21.712 131.012,21.776 130.874,21.85 130.741,21.933 130.614,22.025 130.493,22.126 130.38,22.235 130.275,22.352 130.178,22.476 130.091,22.606 130.012,22.742 129.943,22.883 129.884,23.029 129.836,23.178 129.798,23.331 129.771,23.485 129.754,23.641 129.749,23.798 ; 136.199,86.178 136.201,86.234 136.207,86.29 136.216,86.345 136.23,86.399 136.247,86.452 136.268,86.504 136.292,86.554 136.32,86.602 136.352,86.649 136.386,86.693 136.423,86.734 136.463,86.773 136.506,86.809 136.551,86.842 136.599,86.871 136.648,86.897 136.699,86.92 136.752,86.939 136.805,86.955 136.86,86.966 136.915,86.974 136.971,86.978 137.027,86.978 137.082,86.974 137.138,86.966 137.192,86.955 137.246,86.939 137.298,86.92 137.349,86.897 137.399,86.871 137.446,86.842 137.491,86.809 137.534,86.773 137.574,86.734 137.612,86.693 137.646,86.649 137.677,86.602 137.705,86.554 137.73,86.504 137.751,86.452 137.768,86.399 137.781,86.345 137.791,86.29 137.797,86.234 137.799,86.178 137.797,86.123 137.791,86.067 137.781,86.012 137.768,85.958 137.751,85.905 137.73,85.853 137.705,85.803 137.677,85.754 137.646,85.708 137.612,85.664 137.574,85.623 137.534,85.584 137.491,85.548 137.446,85.515 137.399,85.486 137.349,85.459 137.298,85.437 137.246,85.418 137.192,85.402 137.138,85.391 137.082,85.383 137.027,85.379 136.971,85.379 136.915,85.383 136.86,85.391 136.805,85.402 136.752,85.418 136.699,85.437 136.648,85.459 136.599,85.486 136.551,85.515 136.506,85.548 136.463,85.584 136.423,85.623 136.386,85.664 136.352,85.708 136.32,85.754 136.292,85.803 136.268,85.853 136.247,85.905 136.23,85.958 136.216,86.012 136.207,86.067 136.201,86.123 136.199,86.178 ; 156.249,81.098 156.254,81.255 156.271,81.412 156.298,81.566 156.336,81.719 156.384,81.868 156.443,82.014 156.512,82.155 156.591,82.291 156.678,82.421 156.775,82.545 156.88,82.661 156.993,82.77 157.114,82.871 157.241,82.964 157.374,83.047 157.512,83.121 157.656,83.185 157.803,83.238 157.954,83.282 158.108,83.314 158.264,83.336 158.42,83.347 158.577,83.347 158.734,83.336 158.889,83.314 159.043,83.282 159.194,83.238 159.342,83.185 159.485,83.121 159.624,83.047 159.757,82.964 159.884,82.871 160.004,82.77 160.117,82.661 160.222,82.545 160.319,82.421 160.407,82.291 160.485,82.155 160.554,82.014 160.613,81.868 160.662,81.719 160.7,81.566 160.727,81.412 160.743,81.255 160.749,81.098 160.743,80.941 160.727,80.785 160.7,80.631 160.662,80.478 160.613,80.329 160.554,80.183 160.485,80.042 160.407,79.906 160.319,79.776 160.222,79.652 160.117,79.535 160.004,79.426 159.884,79.325 159.757,79.233 159.624,79.15 159.485,79.076 159.342,79.012 159.194,78.958 159.043,78.915 158.889,78.883 158.734,78.861 158.577,78.85 158.42,78.85 158.264,78.861 158.108,78.883 157.954,78.915 157.803,78.958 157.656,79.012 157.512,79.076 157.374,79.15 157.241,79.233 157.114,79.325 156.993,79.426 156.88,79.535 156.775,79.652 156.678,79.776 156.591,79.906 156.512,80.042 156.443,80.183 156.384,80.329 156.336,80.478 156.298,80.631 156.271,80.785 156.254,80.941 156.249,81.098
  lines w0.254: -0.001,6.998 -0.001,53.068 0.011,53.417 0.047,53.764 0.108,54.108 0.192,54.447 0.3,54.778 0.431,55.102 0.584,55.416 0.759,55.718 0.954,56.007 1.169,56.282 1.402,56.542 1.653,56.784 1.92,57.008 2.203,57.214 2.499,57.399 2.807,57.562 3.126,57.704 3.454,57.824 3.789,57.92 4.131,57.992 4.476,58.041 4.824,58.065 4.999,58.068 4.999,76.953 5.05,78.421 5.204,79.882 5.459,81.329 5.814,82.754 6.268,84.151 6.818,85.513 7.462,86.833 8.197,88.106 9.018,89.323 9.922,90.481 10.905,91.572 11.962,92.593 13.087,93.537 14.276,94.4 15.521,95.179 16.818,95.868 18.16,96.466 19.541,96.968 20.953,97.373 22.389,97.679 23.844,97.883 25.309,97.986 26.044,97.998 146.999,97.998 148.533,97.945 150.061,97.784 151.573,97.518 153.063,97.146 154.523,96.672 155.947,96.096 157.327,95.423 158.657,94.655 159.93,93.797 161.14,92.851 162.281,91.824 163.348,90.719 164.335,89.543 165.238,88.301 166.051,86.998 166.772,85.643 167.397,84.24 167.922,82.797 168.345,81.321 168.665,79.819 168.878,78.298 168.985,76.766 168.999,75.998 168.999,58.068 169.348,58.056 169.695,58.02 170.038,57.959 170.377,57.875 170.709,57.767 171.032,57.636 171.346,57.483 171.648,57.309 171.938,57.113 172.213,56.899 172.472,56.665 172.714,56.414 172.939,56.147 173.144,55.864 173.329,55.568 173.493,55.26 173.635,54.941 173.754,54.613 173.85,54.278 173.923,53.937 173.971,53.591 173.996,53.243 173.999,53.068 173.999,6.998 173.982,6.51 173.931,6.024 173.846,5.543 173.728,5.069 173.577,4.604 173.394,4.151 173.179,3.712 172.935,3.289 172.662,2.884 172.361,2.499 172.034,2.136 171.683,1.796 171.308,1.482 170.913,1.195 170.499,0.936 170.067,0.707 169.621,0.508 169.162,0.341 168.692,0.206 168.214,0.105 167.73,0.037 167.243,0.003 166.999,-0.002 119.999,-0.002 119.999,54.998 119.998,55.033 119.993,55.103 119.984,55.172 119.969,55.24 119.95,55.307 119.926,55.373 119.898,55.437 119.865,55.498 119.828,55.558 119.787,55.614 119.742,55.668 119.693,55.718 119.642,55.764 119.587,55.807 119.529,55.846 119.468,55.881 119.406,55.912 119.341,55.938 119.274,55.96 119.207,55.977 119.138,55.989 119.069,55.996 118.999,55.998 88.499,55.998 88.499,81.998 88.498,82.033 88.493,82.103 88.484,82.172 88.469,82.24 88.45,82.307 88.426,82.373 88.398,82.437 88.365,82.498 88.328,82.558 88.287,82.614 88.242,82.668 88.193,82.718 88.142,82.764 88.087,82.807 88.029,82.846 87.968,82.881 87.906,82.912 87.841,82.938 87.774,82.96 87.707,82.977 87.638,82.989 87.569,82.996 87.499,82.998 49.499,82.998 49.464,82.998 49.394,82.993 49.325,82.983 49.257,82.969 49.19,82.949 49.124,82.926 49.06,82.897 48.999,82.864 48.94,82.827 48.883,82.786 48.83,82.742 48.779,82.693 48.733,82.641 48.69,82.586 48.651,82.528 48.616,82.468 48.585,82.405 48.559,82.34 48.538,82.274 48.521,82.206 48.509,82.138 48.501,82.068 48.499,81.998 48.499,-0.002 6.999,-0.002 6.51,0.015 6.025,0.066 5.543,0.151 5.069,0.27 4.605,0.421 4.152,0.604 3.712,0.818 3.289,1.062 2.884,1.335 2.499,1.636 2.136,1.963 1.797,2.314 1.483,2.689 1.196,3.084 0.937,3.498 0.707,3.93 0.508,4.376 0.341,4.835 0.207,5.305 0.105,5.783 0.037,6.267 0.003,6.754 -0.001,6.998

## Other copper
Top Layer:
  rectangle net PUSH_B: 102.174,83.342 118.303,85.354
  rectangle net PUSH_B: 50.236,83.405 97.753,85.418
  rectangle net GND: 147.595,39.944 154.254,42.721
  rectangle net GND: 161.086,16.906 166.136,33.124
  rectangle net GND: 80.534,91.115 123.877,93.805
  rectangle net BAT_12V: 103.392,95.382 147.814,97.144
  rectangle net BAT_12V: 167.182,56.41 168.624,76.626
  rectangle net BAT_12V: 172.31,7.293 173.753,52.772
  rectangle net BAT_12V: 170.25,4.917 171.356,5.829
  rectangle net GND: 37.133,90.683 63.183,94.747
  rectangle net GND: 24.463,95.383 91.307,97.617
  rectangle: 103.528,95.943 106.195,97.458
  rectangle net GND: 18.711,19.556 22.02,49.464
  rectangle net NetDS1_1: 29.905,40.507 31.695,45.648
  rectangle net NetDS1_1: 20.745,26.224 48.303,30.683
  rectangle net GND: 5.218,17.502 39.202,27.229
  rectangle net GND: 8.288,0.179 48.207,6.492
  rectangle net GND: 2.403,3.442 48.286,19.877
  rectangle net GND: 0.324,6.675 7.995,53.485
  rectangle: 117.712,74.75 118.718,76.021
  rectangle net LED+: 112.932,74.906 116.39,75.859
  rectangle net BAT_12V: 48.303,87.193 65.985,89.006
  rectangle net BAT_12V: 70.851,87.18 121.737,89.131
  rectangle net NetDS1_1: 7.745,47.136 21.72,52.018
  rectangle net GND: 5.075,56.825 7.993,77.077
  rectangle net PUSH_B: 45.918,38.581 47.923,81.008
  rectangle net NetSW1_3: 125.006,49.913 125.866,61.733
  region net NetDS1_1: 50.317,97.499 68.084,97.499 cw(c68.084,94.959) 70.479,95.807 61.017,95.193
  region net GND: 163.21,73.865 160.624,83.482 cw(c155.033,77.546) 163.183,77.291
  region net GND: 153.639,77.148 153.639,84.691 ccw(c149.429,85.354) 150.092,89.564 141.283,89.564 141.283,86.31 cw(c138.743,86.31) 138.743,83.77 136.14,83.77 ccw(c136.627,81.117) 133.975,80.63 133.975,70.082 ccw(c137.139,70.617) 137.675,67.452 147.786,67.452
  region net BAT_12V: 131.965,96.376 ccw(c134.319,96.376) 134.319,94.022 147.609,94.022 ccw(c147.609,94.065) 147.652,94.065 147.652,96.248
  region net GND: 123.798,91.143 126.797,90.492 cw(c126.763,90.457) 126.797,90.423 126.797,90.864 ccw(c134.917,97.644) 133.97,87.109 142.793,88.841 cw(c140.598,105.209) 130.576,92.083 127.71,93.794 123.705,93.794
  region net GND: 152.623,56.648 152.623,41.274 155.066,41.274 155.066,46.539 ccw(c154.818,47.082) 155.361,47.33 155.361,47.592 ccw(c155.361,48.224) 155.992,48.224
  region net GND: 161.219,82.871 158.886,85.569 ccw(c144.488,72.466) 145.403,91.912
  region net GND: 162.019,61.721 158.505,59.518 153.102,57.996 157.212,48.966 cw(c156.738,43.105) 161.219,46.913 160.658,42.845 161.513,41.185 ccw(c162.574,39.933) 160.938,40.067 161.513,38.802 cw(c161.667,35.21) 164.098,37.859 164.769,38.248 166.474,38.535 166.474,40.953 166.474,46.221 166.474,51.685 ccw(c162.254,51.565) 164.935,54.826 163.308,55.595
  region net GND: 161.593,80.746 163.192,74.972 ccw(c163.266,74.958) 163.204,74.916 163.154,57.322 cw(c162.122,57.572) 162.675,56.665 161.94,55.931
  region net GND: 162.046,72.896 162.046,73.102 161.641,81.059 cw(c159.865,81.059) 161.121,79.803 157.266,75.948 158.066,75.147 cw(c156.27,73.351) 158.81,73.351 158.81,70.874
  region net GND: 153.051,87.726 158.67,84.785 ccw(c158.889,84.595) 158.821,84.313 ccw(c161.446,78.338) 155.257,80.41 152.795,82.871
  region: 154.56,82.977 156.99,83.464 156.674,83.282 ccw(c158.732,81.146) 155.767,81.201 156.003,78.49
  region net GND: 159.922,74.244 160.139,78.845 cw(c158.653,80.331) 158.653,78.229 154.543,78.229
  region net GND: 156.414,53.073 161.336,60.244 ccw(c159.54,62.04) 162.08,62.04 162.08,73.049 159.525,73.049 cw(c159.525,75.589) 157.729,73.793 148.423,83.1 143.314,77.991 ccw(c145.11,76.195) 142.57,76.195 142.57,69.973 ccw(c145.11,69.973) 145.11,67.433 146.649,67.433
  region net GND: 157.103,34.28 ccw(c151.402,34.517) 151.638,40.218 149.816,40.218
  region net GND: 152.047,41.961 157.878,40.23 cw(c162.058,37.398) 166.466,39.862 166.466,23.054
  region net GND: 147.275,42.446 162.574,42.446 cw(c160.282,42.197) 160.531,39.906 160.531,36.919
  region net GND: 151.528,41.833 151.528,34.673 ccw(c154.068,34.673) 154.068,32.133 164.321,32.133
  region net GND: 166.352,23.724 166.352,17.785 cw(c163.812,17.785) 163.812,15.245 161.557,15.245
  region net GND: 65.507,96.129 65.507,95.847 cw(c62.706,95.847) 62.706,93.046 58.644,93.046 cw(c58.644,95.586) 56.104,95.586 56.104,95.733
  region net GND: 35.06,96.156 35.06,95.605 ccw(c37.6,95.605) 37.6,93.065 55.7,93.065 ccw(c55.7,95.605) 58.24,95.605 58.24,96.063 ccw(c58.286,96.063) 58.286,96.016 69.666,96.016
  region: 63.038,93.021 63.038,93.307 cw(c65.578,93.307) 65.578,95.847 66.262,95.847 ccw(c66.262,95.364) 65.778,95.364 65.778,96.29 cw(c66.02,96.29) 66.02,96.532 66.302,96.532 cw(c66.302,95.425) 67.269,95.966
  region: 112.39,95.893 103.6,95.893 cw(c103.993,97.007) 102.879,97.4
  region: 168.508,56.51 167.245,56.405 cw(c167.245,58.234) 165.416,58.234 165.416,74.162 cw(c167.956,74.162) 167.956,76.702 168.2,76.702
  region net BAT_12V: 173.326,9.588 173.326,7.407 cw(c171.088,8.079) 170.416,5.841
  region net BAT_12V: 173.754,8.701 173.717,6.684 cw(c171.303,6.684) 171.303,4.27 169.894,4.27 ccw(c169.894,4.22) 169.844,4.22
  region net GND: 16.761,47.296 10.854,47.296 ccw(c4.628,44.202) 7.348,50.6 2.813,47.951 ccw(c9.313,45.842) 3.226,42.737 4.096,27.863 ccw(c4.854,41.127) 15.864,33.692 19.096,31.922 18.97,42.737 ccw(c17.383,44.325) 19.628,44.325 19.628,44.829 ccw(c17.813,44.829) 19.096,46.112 18.586,46.622 ccw(c16.79,44.827) 16.79,47.366 16.597,47.366
  region net GND: 153.626,43.939 151.983,41.632 150.248,42.684 151.023,43.866 151.503,43.884
  region net GND: 153.148,82.854 153.148,72.705 161.826,72.705
  region net GND: 73.846,91.103 71.137,95.538 91.336,95.393 94.608,91.103
  region net GND: 62.93,95.914 62.708,95.693 59.856,95.693 59.856,94.447 60.59,93.713
  region: 26.8,68.2 27.406,67.594 22.175,63.383 19.974,65.584 19.974,67.148 19.782,67.339 19.782,68.966 20.197,69.381
  region: 12.361,31.595 12.945,31.011 12.945,26.239 2.273,26.239
  region net NetDS1_1: 21.681,52.763 21.03,52.112 17.575,46.912 20.335,42.451 21.994,44.971
  region: 40.518,26.313 40.518,26.079 38.769,24.444 38.267,25.677 38.267,26.347
  region net GND: 43.465,26.718 48.3,26.718 48.3,17.897
  region net NetDS1_1: 47.673,17.673 47.673,21.636 45.078,24.596 45.268,23.381 42.476,20.589 38.673,22.889 38.133,16.876 42.451,16.414 45.429,17.132
  region: 12.248,4.435 8.562,0.749 8.562,0.595 6.671,0.595 3.583,3.683 3.101,3.683 3.101,4.782 2.985,4.898 2.985,5.284
  region: 12.306,53.01 11.983,53.332 4.113,57.106 0.753,54.13 7.768,49.802 1.38,53.178 7.727,48.935 8.413,48.249 8.897,48.249 8.897,49.863 10.491,51.457
  region net GND: 14.136,79.204 13.426,80.041 13.15,80.796 13.238,81.671 13.426,82.156 13.633,82.471 14.294,83.261 13.15,83.616 12.342,83.616 11.189,82.463 10.981,82.463 10.981,82.359 6.377,81.155 6.088,79.017 7.084,79.017 7.079,78.76 7.236,78.718 6.377,76.509 7.433,72.049 6.907,53.636 15.814,50.98 21.57,50.233 22.14,56.221 22.84,57.03 22.84,72.126 22.84,75.699 22.84,76.648 22.84,76.722 22.84,76.78 22.84,76.804 22.746,83.089 17.798,83.189 17.931,80.702 17.677,79.878 17.233,79.204 16.701,78.973 15.814,78.718 15.084,78.76
  region net GND: 33.054,87.294 39.875,94.688 25.443,97.742 21.086,95.8 19.864,95.777 19.293,94.569 18.925,94.569 7.459,84.939 8.257,79.435 16.136,84.116 21.086,79.165 23.083,82.415 21.861,81.193 19.293,77.372 19.293,67.198 33.054,67.198
  region: 160.256,75.79 160.213,75.832
  region: 53.31,82.104 53.3,82.104
  region net NetSW1_3: 135.977,40.135 125.918,50.195 125.32,50.195 135.685,39.829
  region net NetDS1_1: 113.497,65.811 113.505,65.783 113.622,65.657 113.922,65.4 113.993,65.351
  text "TOP LAYER" at 19.108,102.719 h10
Bottom Layer:
  region: 69.03,87.936 69.031,87.936 69.031,87.947
Multi-Layer:
  pour cut-out: 115.355,75.908 115.911,75.908 116.114,75.705

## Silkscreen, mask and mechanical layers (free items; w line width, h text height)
Top Overlay:
  drawing of 1009 lines, arcs and shapes, not listed
  text "KEM  Date:" at 105.934,57.21 h0.7
  text "97.982 (mm)" at -3.489,36.451 h5 r89.97
  text "12" at 159.094,18.936 h2 r90
  text "6" at 164.616,15.379 h2 r90
  text "7" at 157.933,1.984 h2 r90
Bottom Overlay:
  lines w0.254: 113.48,69.928 121.798,69.928 121.798,77.685 113.48,77.685 113.48,69.928
  text "+ -" at 115.156,72.558 h1.52
  text "LED" at 115.949,71.106 h1
Bottom Paste:
  lines w0.254: 118.251,75.282 118.251,75.907
Top Solder:
  rectangle: 157.67,3.874 162.75,5.831
  region: 162.059,5.822 162.059,4.473 162.714,4.473 162.714,5.822
  region: 158.031,5.219 158.031,4.102 159.468,4.102 159.468,5.219
  rectangle: 162.231,4.531 163.507,5.044
  region: 158.109,4.122 158.109,3.871 159.468,3.871 159.468,4.122
  rectangle: 161.36,4.921 163.728,5.428
  rectangle: 162.596,4.437 163.345,5.703
  rectangle: 163.049,5.364 163.61,5.581
  region: 157.25,9.5 163,9.5 163,8.5 157.25,8.5
  region: 157.837,16.522 159.587,16.522 159.587,12.647 157.837,12.647
  region: 160.875,16.625 162.625,16.625 162.625,12.75 160.875,12.75
  lines w0.254: 159.738,4.673 159.738,4.962
Bottom Solder:
  lines w0.1: 116.448,75.41 ccw(c115.77,75.367) 116.449,75.365 ; 118.874,75.441 ccw(c118.208,75.398) 118.876,75.396
Mechanical 1:
  circle w0.008: c98.625,73.178 r0.49
  circle w0.008: c98.629,70.188 r0.49
  circle w0.1: c99.866,82.088 r0.845
  circle w0.1: c98.618,76.162 r0.566
  circle w0.1: c98.619,76.177 r0.525
  circle w0.1: c98.626,73.182 r0.525
  circle w0.1: c98.612,70.169 r0.525
  circle w0.254: c99.869,64.265 r0.947
  circle w0.1: c161.784,15.814 r0.508
  circle w0.1: c158.792,15.805 r0.517
  circle w0.1: c161.757,13.606 r0.508
  circle w0.1: c158.783,13.606 r0.508
  circle w0.1: c161.794,9.216 r0.508
  circle w0.1: c161.784,11.379 r0.508
  circle w0.1: c161.775,4.799 r0.508
  circle w0.1: c158.773,4.789 r0.508
  circle w0.1: c158.773,9.188 r0.508
Mechanical 13:
  circle w0.1: c99.898,64.259 r0.836
  circle w0.1: c161.786,6.995 r0.533
  circle w0.1: c158.782,7.009 r0.533
  circle w0.1: c158.784,11.422 r0.533
Drill Drawing:
  rectangle: 131.199,91.26 139.66,92.152
  region: 138,89.361 ccw(c140.121,88.006) 138.766,85.885 135.507,83.5 ccw(c138.155,87.594) 142.249,84.946 141.998,89.117
  region: 153.25,88.848 156.212,86.963 ccw(c142.512,71.615) 141.344,92.155 129.953,92.042 ccw(c132.229,93.322) 131.525,90.808 134.679,88.848
  region: 127.707,93.792 128.255,93.792 128.38,93.589 128.38,93.165
  region: 129.385,95.985 132.8,96.104 133.704,95.2 133.059,94.555 133.059,94.429 132.639,94.429 132.531,94.537 131.86,94.537 131.529,94.868 131.152,94.868
  region: 129.03,89.227 135.494,82.763 137.312,82.763 137.312,84.001 134.661,86.652 135.367,87.359 135.367,88.344 135.898,88.344 136.681,89.126
  region: 131.977,92.042 134.546,89.472 134.546,89.445
  lines w0.254: 128.262,93.673 ccw(c131.81,96.637) 131.191,92.056 ; 129.096,96.122 ccw(c134.652,103.037) 135.481,94.205
  lines w2: 121.442,92.031 cw(c122.101,79.078) 135.003,80.394 ; 138.939,86.174 ccw(c137.004,86.174) 138.939,86.174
